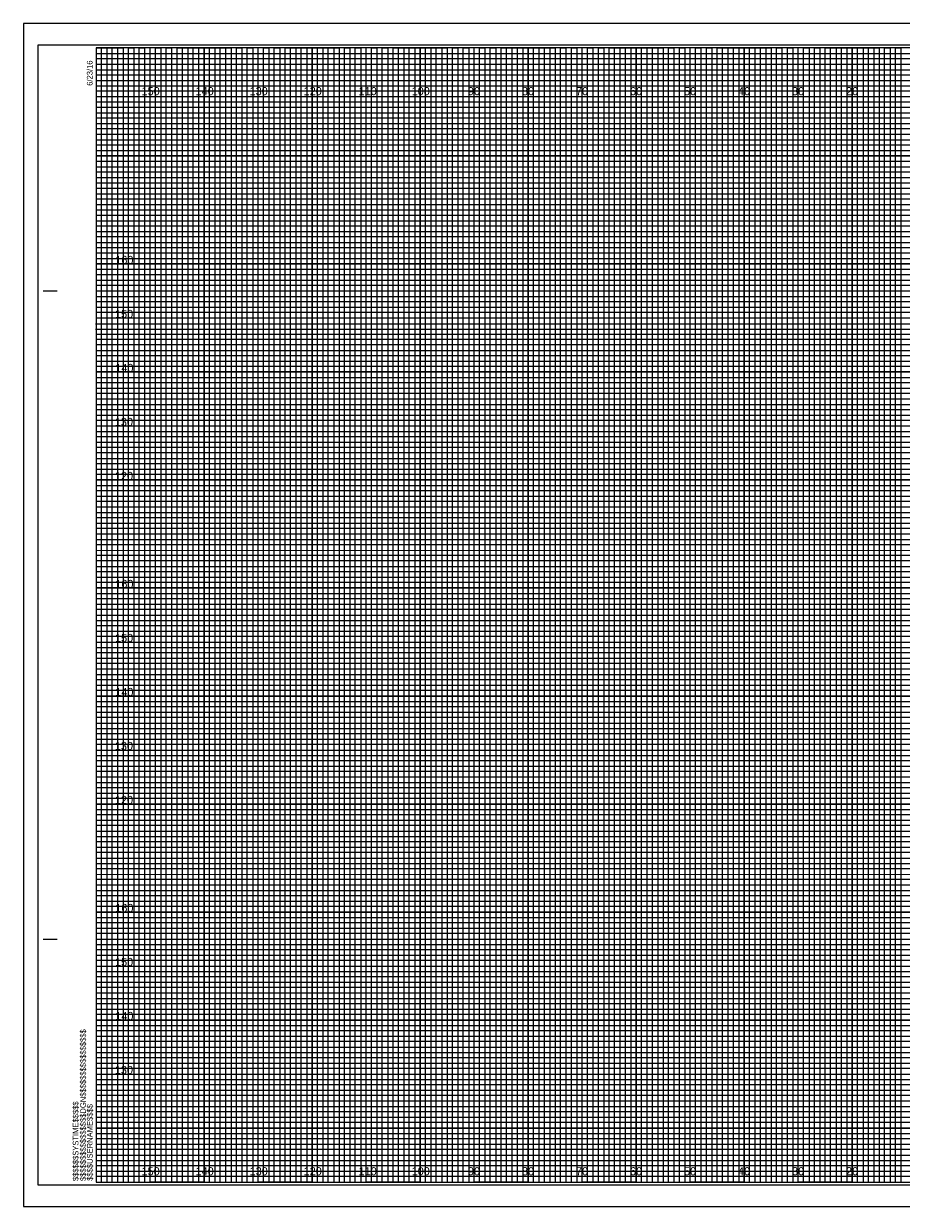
# Model space of a CAD drawing. Extents: x -13 to 323, y -5 to 4834.
# Drawn here: x -13.4 to 149.1, y 2195.5 to 2414.5 of the extents above; entities that cross this region are included whole.
import ezdxf

# ---------------------------------------------------------------- set-up
doc = ezdxf.new("R2010")
doc.units = 0
for name, color, linetype in [('Exist Cross Section Cell', 7, 'Continuous'), ('Exist XS Center Line Elevation Label', 7, 'Continuous'), ('Exist XS Ground Line', 7, 'Continuous'), ('Prop CMT Pvmt Course 1', 7, 'Continuous'), ('Prop CMT Pvmt Course 2', 7, 'Continuous'), ('Prop CMT Pvmt Course 3', 7, 'Continuous'), ('Prop CMT Pvmt Surface Shoulder', 7, 'Continuous'), ('Prop CMT Shld Paved Course 1', 7, 'Continuous'), ('Prop CMT Shld Paved Course 2', 7, 'Continuous'), ('Prop CMT Shld Paved Course 3', 7, 'Continuous'), ('Prop CMT Slope Grass', 7, 'Continuous')]:
    doc.layers.add(name, color=color, linetype=linetype)

msp = doc.modelspace()

# ---------------------------------------------------------------- linework, layer by layer
at = {"layer": 'Exist XS Center Line Elevation Label'}
for points in [[(0, 2410), (5, 2410), (5, 2200), (15, 2200), (15, 2410), (25, 2410), (25, 2200), (35, 2200), (35, 2410), (45, 2410), (45, 2200), (55, 2200), (55, 2410), (65, 2410), (65, 2200), (75, 2200), (75, 2410), (85, 2410), (85, 2200), (95, 2200), (95, 2410), (105, 2410), (105, 2200), (115, 2200), (115, 2410), (125, 2410), (125, 2200), (135, 2200), (135, 2410), (145, 2410), (145, 2200), (155, 2200)], [(0, 2405), (275, 2405)], [(0, 2385), (320, 2385), (320, 2395), (0, 2395)], [(0, 2365), (320, 2365), (320, 2375), (0, 2375)], [(0, 2345), (320, 2345), (320, 2355), (0, 2355)], [(0, 2325), (320, 2325), (320, 2335), (0, 2335)], [(0, 2305), (320, 2305), (320, 2315), (0, 2315)], [(0, 2285), (320, 2285), (320, 2295), (0, 2295)], [(0, 2265), (320, 2265), (320, 2275), (0, 2275)], [(0, 2245), (320, 2245), (320, 2255), (0, 2255)], [(0, 2225), (320, 2225), (320, 2235), (0, 2235)], [(0, 2205), (320, 2205), (320, 2215), (0, 2215)]]:
    msp.add_lwpolyline(points, dxfattribs=at)
at = {"layer": 'Exist XS Ground Line'}
for p, q in [((10, 2410), (0, 2410)), ((10, 2200), (10, 2410)), ((30, 2410), (20, 2410)), ((20, 2410), (20, 2200)), ((30, 2200), (30, 2410)), ((50, 2410), (40, 2410)), ((40, 2410), (40, 2200)), ((50, 2200), (50, 2410)), ((70, 2410), (60, 2410)), ((60, 2410), (60, 2200)), ((70, 2200), (70, 2410)), ((90, 2410), (80, 2410)), ((80, 2410), (80, 2200)), ((90, 2200), (90, 2410)), ((110, 2410), (100, 2410)), ((100, 2410), (100, 2200)), ((110, 2200), (110, 2410)), ((130, 2410), (120, 2410)), ((120, 2410), (120, 2200)), ((130, 2200), (130, 2410)), ((150, 2410), (140, 2410)), ((140, 2410), (140, 2200)), ((20, 2200), (10, 2200)), ((40, 2200), (30, 2200)), ((60, 2200), (50, 2200)), ((80, 2200), (70, 2200)), ((100, 2200), (90, 2200)), ((120, 2200), (110, 2200)), ((140, 2200), (130, 2200))]:
    msp.add_line(p, q, dxfattribs=at)
for points in [[(0, 2400), (320, 2400), (320, 2390), (0, 2390)], [(0, 2380), (320, 2380), (320, 2370), (0, 2370)], [(0, 2360), (320, 2360), (320, 2350), (0, 2350)], [(0, 2340), (320, 2340), (320, 2330), (0, 2330)], [(0, 2320), (320, 2320), (320, 2310), (0, 2310)], [(0, 2300), (320, 2300), (320, 2290), (0, 2290)], [(0, 2280), (320, 2280), (320, 2270), (0, 2270)], [(0, 2260), (320, 2260), (320, 2250), (0, 2250)], [(0, 2240), (320, 2240), (320, 2230), (0, 2230)], [(0, 2220), (320, 2220), (320, 2210), (0, 2210)]]:
    msp.add_lwpolyline(points, dxfattribs=at)
at = {"layer": 'Prop CMT Pvmt Course 1'}
for points in [[(0, 2200), (1, 2200), (1, 2410), (2, 2410), (2, 2200)], [(2, 2200), (3, 2200), (3, 2410), (4, 2410), (4, 2200)], [(5, 2200), (6, 2200), (6, 2410), (7, 2410), (7, 2200)], [(7, 2200), (8, 2200), (8, 2410), (9, 2410), (9, 2200)], [(10, 2200), (11, 2200), (11, 2410), (12, 2410), (12, 2200)], [(12, 2200), (13, 2200), (13, 2410), (14, 2410), (14, 2200)], [(15, 2200), (16, 2200), (16, 2410), (17, 2410), (17, 2200)], [(17, 2200), (18, 2200), (18, 2410), (19, 2410), (19, 2200)], [(20, 2200), (21, 2200), (21, 2410), (22, 2410), (22, 2200)], [(22, 2200), (23, 2200), (23, 2410), (24, 2410), (24, 2200)], [(25, 2200), (26, 2200), (26, 2410), (27, 2410), (27, 2200)], [(27, 2200), (28, 2200), (28, 2410), (29, 2410), (29, 2200)], [(30, 2200), (31, 2200), (31, 2410), (32, 2410), (32, 2200)], [(32, 2200), (33, 2200), (33, 2410), (34, 2410), (34, 2200)], [(35, 2200), (36, 2200), (36, 2410), (37, 2410), (37, 2200)], [(37, 2200), (38, 2200), (38, 2410), (39, 2410), (39, 2200)], [(40, 2200), (41, 2200), (41, 2410), (42, 2410), (42, 2200)], [(42, 2200), (43, 2200), (43, 2410), (44, 2410), (44, 2200)], [(45, 2200), (46, 2200), (46, 2410), (47, 2410), (47, 2200)], [(47, 2200), (48, 2200), (48, 2410), (49, 2410), (49, 2200)], [(50, 2200), (51, 2200), (51, 2410), (52, 2410), (52, 2200)], [(52, 2200), (53, 2200), (53, 2410), (54, 2410), (54, 2200)], [(55, 2200), (56, 2200), (56, 2410), (57, 2410), (57, 2200)], [(57, 2200), (58, 2200), (58, 2410), (59, 2410), (59, 2200)], [(60, 2200), (61, 2200), (61, 2410), (62, 2410), (62, 2200)], [(62, 2200), (63, 2200), (63, 2410), (64, 2410), (64, 2200)], [(65, 2200), (66, 2200), (66, 2410), (67, 2410), (67, 2200)], [(67, 2200), (68, 2200), (68, 2410), (69, 2410), (69, 2200)], [(70, 2200), (71, 2200), (71, 2410), (72, 2410), (72, 2200)], [(72, 2200), (73, 2200), (73, 2410), (74, 2410), (74, 2200)], [(75, 2200), (76, 2200), (76, 2410), (77, 2410), (77, 2200)], [(77, 2200), (78, 2200), (78, 2410), (79, 2410), (79, 2200)], [(80, 2200), (81, 2200), (81, 2410), (82, 2410), (82, 2200)], [(82, 2200), (83, 2200), (83, 2410), (84, 2410), (84, 2200)], [(85, 2200), (86, 2200), (86, 2410), (87, 2410), (87, 2200)], [(87, 2200), (88, 2200), (88, 2410), (89, 2410), (89, 2200)], [(90, 2200), (91, 2200), (91, 2410), (92, 2410), (92, 2200)], [(92, 2200), (93, 2200), (93, 2410), (94, 2410), (94, 2200)], [(95, 2200), (96, 2200), (96, 2410), (97, 2410), (97, 2200)], [(97, 2200), (98, 2200), (98, 2410), (99, 2410), (99, 2200)], [(100, 2200), (101, 2200), (101, 2410), (102, 2410), (102, 2200)], [(102, 2200), (103, 2200), (103, 2410), (104, 2410), (104, 2200)], [(105, 2200), (106, 2200), (106, 2410), (107, 2410), (107, 2200)], [(107, 2200), (108, 2200), (108, 2410), (109, 2410), (109, 2200)], [(110, 2200), (111, 2200), (111, 2410), (112, 2410), (112, 2200)], [(112, 2200), (113, 2200), (113, 2410), (114, 2410), (114, 2200)], [(115, 2200), (116, 2200), (116, 2410), (117, 2410), (117, 2200)], [(117, 2200), (118, 2200), (118, 2410), (119, 2410), (119, 2200)], [(120, 2200), (121, 2200), (121, 2410), (122, 2410), (122, 2200)], [(122, 2200), (123, 2200), (123, 2410), (124, 2410), (124, 2200)], [(125, 2200), (126, 2200), (126, 2410), (127, 2410), (127, 2200)], [(127, 2200), (128, 2200), (128, 2410), (129, 2410), (129, 2200)], [(130, 2200), (131, 2200), (131, 2410), (132, 2410), (132, 2200)], [(132, 2200), (133, 2200), (133, 2410), (134, 2410), (134, 2200)], [(135, 2200), (136, 2200), (136, 2410), (137, 2410), (137, 2200)], [(137, 2200), (138, 2200), (138, 2410), (139, 2410), (139, 2200)], [(140, 2200), (141, 2200), (141, 2410), (142, 2410), (142, 2200)], [(142, 2200), (143, 2200), (143, 2410), (144, 2410), (144, 2200)], [(145, 2200), (146, 2200), (146, 2410), (147, 2410), (147, 2200)], [(147, 2200), (148, 2200), (148, 2410), (149, 2410), (149, 2200)]]:
    msp.add_lwpolyline(points, dxfattribs=at)
at = {"layer": 'Prop CMT Pvmt Course 2'}
for p, q in [((323.3, 2414.5), (-13.4, 2414.5)), ((-13.4, 2414.5), (-13.4, 2195.5)), ((-13.4, 2195.5), (323.3, 2195.5))]:
    msp.add_line(p, q, dxfattribs=at)
at = {"layer": 'Prop CMT Pvmt Surface Shoulder'}
for p, q in [((-9.8, 2365), (-7.3, 2365)), ((-9.7, 2365), (-7.2, 2365)), ((-9.8, 2245), (-7.3, 2245)), ((-9.7, 2245), (-7.2, 2245)), ((0, 2200), (0, 2200)), ((0, 2200), (0, 2200)), ((0, 2200), (0, 2200)), ((0, 2200), (0, 2200)), ((0, 2200), (0, 2200)), ((0, 2200), (0, 2200)), ((0, 2200), (0, 2200))]:
    msp.add_line(p, q, dxfattribs=at)
msp.add_lwpolyline([(320, 2410), (0, 2410), (0, 2200), (320, 2200)], close=True, dxfattribs=at)
at = {"layer": 'Prop CMT Shld Paved Course 1'}
msp.add_lwpolyline([(-13.4, 2195.5), (323.3, 2195.5), (323.3, 2414.5), (-13.4, 2414.5)], close=True, dxfattribs=at)
at = {"layer": 'Prop CMT Shld Paved Course 2'}
msp.add_lwpolyline([(-10.8, 2199.5), (322.4, 2199.5), (322.4, 2410.5), (-10.8, 2410.5)], close=True, dxfattribs=at)
at = {"layer": 'Prop CMT Shld Paved Course 3'}
for p, q in [((10, 2200), (10, 2410)), ((20, 2200), (20, 2410)), ((30, 2200), (30, 2410)), ((40, 2200), (40, 2410)), ((50, 2200), (50, 2410)), ((60, 2200), (60, 2410)), ((70, 2200), (70, 2410)), ((80, 2200), (80, 2410)), ((90, 2200), (90, 2410)), ((100, 2200), (100, 2410)), ((110, 2200), (110, 2410)), ((120, 2200), (120, 2410)), ((130, 2200), (130, 2410)), ((140, 2200), (140, 2410)), ((0, 2400), (320, 2400)), ((0, 2390), (320, 2390)), ((0, 2380), (320, 2380)), ((0, 2370), (320, 2370)), ((0, 2360), (320, 2360)), ((0, 2350), (320, 2350)), ((0, 2340), (320, 2340)), ((0, 2330), (320, 2330)), ((0, 2320), (320, 2320)), ((0, 2310), (320, 2310)), ((0, 2300), (320, 2300)), ((0, 2290), (320, 2290)), ((0, 2280), (320, 2280)), ((0, 2270), (320, 2270)), ((0, 2260), (320, 2260)), ((0, 2250), (320, 2250)), ((0, 2240), (320, 2240)), ((0, 2230), (320, 2230)), ((0, 2220), (320, 2220)), ((0, 2210), (320, 2210))]:
    msp.add_line(p, q, dxfattribs=at)
at = {"layer": 'Prop CMT Slope Grass'}
for p, q in [((0, 2409), (260, 2409)), ((260, 2407.98), (0, 2407.98)), ((0, 2407.98), (0, 2407)), ((0, 2407), (260, 2407)), ((260, 2405.89), (0, 2405.89)), ((0, 2405.89), (0, 2404)), ((0, 2404), (320, 2404))]:
    msp.add_line(p, q, dxfattribs=at)
for points in [[(0, 2403), (270, 2403), (320, 2403), (320, 2402), (0, 2402)], [(0, 2401), (320, 2401), (320, 2399), (0, 2399)], [(0, 2398), (320, 2398), (320, 2397), (0, 2396.98)], [(0, 2396), (320, 2396), (320, 2394), (0, 2394)], [(0, 2393), (320, 2393), (320, 2392), (0, 2392)], [(0, 2391), (320, 2391), (320, 2389), (0, 2389)], [(0, 2388), (320, 2388), (320, 2387), (0, 2387)], [(0, 2386), (320, 2386), (320, 2384), (0, 2384)], [(0, 2383), (320, 2383), (320, 2382), (0, 2382)], [(0, 2381), (320, 2381), (320, 2379), (0, 2379)], [(0, 2378), (320, 2378), (320, 2377), (0, 2377)], [(0, 2376), (320, 2376), (320, 2373.95), (320, 2373), (320, 2372), (0, 2372)], [(0, 2374), (320, 2374), (320, 2373), (0, 2373)], [(0, 2371), (320, 2371), (320, 2369), (0, 2369.03)], [(0, 2369.03), (320, 2369), (320, 2368), (0, 2368)], [(0, 2367), (320, 2367), (320, 2366), (0, 2366)], [(0, 2364), (320, 2364), (320, 2363), (0, 2363)], [(0, 2362), (320, 2362), (320, 2361), (0, 2361)], [(-0.07, 2358.89), (320, 2358.89), (320, 2357.88), (-0.07, 2357.88)], [(0, 2357), (320, 2357), (320, 2356), (0, 2356)], [(0, 2354), (320, 2354), (320, 2353), (0, 2353)], [(0, 2352), (320, 2352), (320, 2351), (0, 2351)], [(0, 2349), (320, 2349), (320, 2348), (0, 2348)], [(0, 2347), (320, 2347), (320, 2346), (0, 2346)], [(0, 2344), (320, 2344), (320, 2343), (0, 2343)], [(0, 2342), (320, 2342), (320, 2341), (0, 2341)], [(0, 2339), (320, 2339), (319.99, 2337.98), (0, 2338)], [(0, 2337), (320, 2337), (320, 2336), (0, 2336)], [(0, 2334), (320, 2334), (320, 2333), (0, 2333)], [(0, 2332), (320, 2332), (320, 2331), (0, 2331)], [(0, 2329), (320, 2329), (320, 2328), (0, 2328)], [(0, 2327), (320, 2327), (320, 2326), (0, 2326)], [(0, 2324), (320, 2324), (320, 2323), (0, 2323)], [(0, 2322), (320, 2322), (320, 2321), (0, 2321)], [(0, 2319), (320, 2319), (320, 2318), (0, 2318)], [(0, 2316.99), (320.07, 2316.91), (320, 2316), (0, 2316)], [(0, 2314), (320, 2314), (320, 2313), (0, 2313)], [(0, 2312), (320, 2312), (320, 2311), (0, 2311)], [(0, 2309), (320, 2309), (320, 2308), (0, 2308)], [(0, 2307), (320, 2307), (320, 2306), (0, 2306)], [(0, 2304), (320, 2304), (320, 2303), (0, 2303)], [(0, 2302), (320, 2302), (320, 2301), (0, 2301)], [(0, 2299), (320, 2299), (320, 2298), (0, 2298)], [(0, 2297), (320, 2297), (320, 2296), (0, 2296)], [(0, 2294), (320, 2294), (320, 2293), (0, 2293)], [(0, 2292), (320, 2292), (320, 2291), (0, 2291)], [(0, 2289), (320, 2289), (320, 2288), (0, 2288)], [(0, 2287), (320, 2287), (320, 2286), (0, 2286)], [(0, 2284), (320, 2284), (320, 2283), (0, 2283)], [(0, 2282), (320, 2282), (320, 2281), (0, 2281)], [(0, 2279), (320, 2279), (319.99, 2277.98), (0, 2278)], [(0, 2277), (320, 2277), (320, 2276), (0, 2276)], [(0, 2274), (320, 2274), (320, 2273), (0, 2273)], [(0, 2272), (320, 2272), (320, 2271), (0, 2271)], [(0, 2269), (320, 2269), (320, 2268), (0, 2268)], [(0, 2267), (320, 2267), (320, 2266), (0, 2266)], [(0, 2264), (320, 2264), (320, 2263), (0, 2263)], [(0, 2262), (320, 2262), (320, 2261), (0, 2261)], [(0, 2259), (320, 2259), (320, 2258), (0, 2258)], [(0, 2256.99), (320.07, 2256.91), (320, 2256), (0, 2256)], [(0, 2254), (320, 2254), (320, 2253), (0, 2253)], [(0, 2252), (320, 2252), (320, 2251), (0, 2251)], [(0, 2249), (320, 2249), (320, 2248), (0, 2248)], [(0, 2247), (320, 2247), (320, 2246), (0, 2246)], [(0, 2244), (320, 2244), (320, 2243), (0, 2243)], [(0, 2242), (320, 2242), (320, 2241), (0, 2241)], [(0, 2239), (320, 2239), (320, 2238), (0, 2238)], [(0, 2237), (320, 2237), (320, 2236), (0, 2236)], [(0, 2234), (320, 2234), (320, 2233), (0, 2233)], [(0, 2232), (320, 2232), (320, 2231), (0, 2231)], [(0, 2229), (320, 2229), (320, 2228), (0, 2228)], [(0, 2227), (320, 2227), (320, 2226), (0, 2226)], [(0, 2224), (320, 2224), (320, 2223), (0, 2223)], [(0, 2222), (320, 2222), (320, 2221), (0, 2221)], [(0, 2219), (320, 2219), (320, 2218), (0, 2218)], [(0, 2217), (320, 2217), (320, 2216), (0, 2216)], [(0, 2214), (320, 2214), (320, 2213), (0, 2213)], [(0, 2212), (320, 2212), (320, 2211), (0, 2211)], [(0, 2209), (320, 2209), (320, 2208), (0, 2208)], [(0, 2207), (320, 2207), (320, 2206), (0, 2206)], [(0, 2204), (320, 2204), (320, 2203), (0, 2203)], [(0, 2202), (320, 2202), (320, 2201), (0, 2201)]]:
    msp.add_lwpolyline(points, dxfattribs=at)

# ---------------------------------------------------------------- texts
at = {"layer": 'Exist Cross Section Cell'}
for s, p in [('150', (8.44, 2401.25)), ('140', (18.44, 2401.25)), ('130', (28.44, 2401.25)), ('120', (38.44, 2401.25)), ('110', (48.62, 2401.25)), ('100', (58.44, 2401.25)), ('90', (68.86, 2401.25)), ('80', (78.86, 2401.25)), ('70', (88.86, 2401.25)), ('60', (98.86, 2401.25)), ('50', (108.86, 2401.25)), ('40', (118.86, 2401.25)), ('30', (128.86, 2401.25)), ('20', (138.86, 2401.25)), ('150', (8.44, 2201.25)), ('140', (18.44, 2201.25)), ('130', (28.44, 2201.25)), ('120', (38.44, 2201.25)), ('110', (48.62, 2201.25)), ('100', (58.44, 2201.25)), ('90', (68.86, 2201.25)), ('80', (78.86, 2201.25)), ('70', (88.86, 2201.25)), ('60', (98.86, 2201.25)), ('50', (108.86, 2201.25)), ('40', (118.86, 2201.25)), ('30', (128.86, 2201.25)), ('20', (138.86, 2201.25))]:
    msp.add_text(s, height=1.5, dxfattribs=at).set_placement(p)
at = {"layer": 'Prop CMT Pvmt Course 3'}
for s, p in [('160', (3.57, 2370)), ('150', (3.52, 2360)), ('140', (3.57, 2350)), ('130', (3.49, 2340)), ('120', (3.5, 2330)), ('160', (3.57, 2310)), ('150', (3.52, 2300)), ('140', (3.57, 2290)), ('130', (3.49, 2280)), ('120', (3.5, 2270)), ('160', (3.57, 2250)), ('150', (3.52, 2240)), ('140', (3.57, 2230)), ('130', (3.49, 2220))]:
    msp.add_text(s, height=1.5, dxfattribs=at).set_placement(p)
at = {"layer": 'Prop CMT Pvmt Surface Shoulder'}
for s, p in [('6/23/16', (-0.65, 2403)), ('$$$$$$$$$$$$$$$$DGN$$$$$$$$$$$$$$$$', (-1.88, 2200.18)), ('$$$$$$SYSTIME$$$$$', (-3.26, 2200.18)), ('$$$$USERNAME$$$$', (-0.62, 2200.23))]:
    msp.add_text(s, height=1.05, rotation=90, dxfattribs=at).set_placement(p)

doc.saveas('drawing.dxf')
